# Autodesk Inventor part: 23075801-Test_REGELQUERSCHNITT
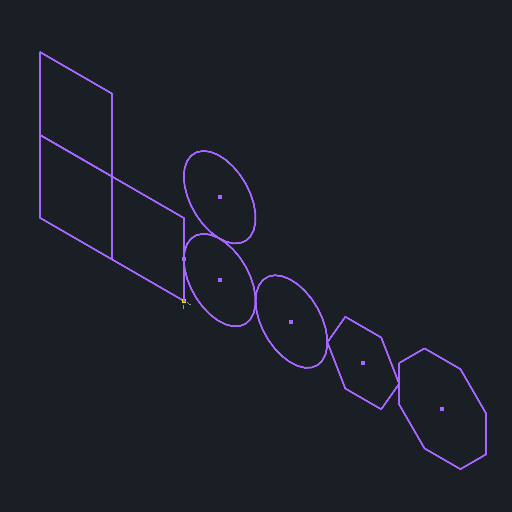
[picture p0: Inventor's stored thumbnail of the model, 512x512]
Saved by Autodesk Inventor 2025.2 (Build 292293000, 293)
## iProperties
Company: Ed. Züblin AG
Created: 2025-03
Part Number: 23075801-Test_REGELQUERSCHNITT
Material: Stahlbeton C30/37
Document SubType Name: Modeling
Designer: FrodlSte
Density: 2.5 g/cm^3
Appearance: Beton C30/37
z_Bereich: Tunnelbau
z_Direktion: Tief- und Tunnelbau
z_Konzerneinheit: Zentrale Technik
z_Matchkey: =<z_Matchkey_010>_<z_Matchkey_020>_<z_Matchkey_030>_<z_Matchkey_040>_<z_Matchkey_050>_<z_Matchkey_060>_<z_Matchkey_070>_<z_Matchkey_080>_<z_Matchkey_090>_<z_Mat
cpiComponentType: Attribut
cpiFitMatchkey: =<z_Matchkey>
z_Matchkey_010: xxxxx
z_Matchkey_020: 5DTUB
z_Matchkey_030: xxx
z_Matchkey_040: xxx
z_Matchkey_050: xxx
z_Matchkey_060: xxx
z_Matchkey_070: xxx
z_Matchkey_080: xxx
z_Matchkey_090: xxx
z_Matchkey_100: xxx
z_Matchkey_110: xxx
z_Matchkey_120: xxxxxxx
z_Matchkey_130: xxxx
z_Matchkey_140: xxxx
DocNumber: 23075801-Test_Skelett.ipt
Folder: DL23075801-DE-Pfaffensteigtunnel\BIM\Testmodell
VDS_Category: 09 - BIM - Konstruktion
d4: 1,000 m
d5: 1,000 m
d6: 1,000 m
d7: 1,000 m
d8: 1,000 m
d9: 1,000 m
d10: 1,000 m
d11: 1,000 m
d12: 1,000 m
d13: 0,500 m
d15: 0,500 m
AS_Ta_IST: 0,300 m
AS_Abs_L_So: 2,000 m
AS_Td_IST: 3,000 m
AS_Ti_IST: 3,000 m
AS_U_IST: 4,000 m
IS_T_b_M1: 1,000 m
AS_Abs_L_Ka: 1,000 m
DR_D_i: 0,250 m
AS_Dak_IST: 0,030 m
AS_Dad_IST: 0,010 m
Author: FrodlSte
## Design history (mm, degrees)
node "Blöcke"
  sketch "Baugruppe_Quadrate"
    geometry: L1 (0, 0)-(1000, 0); L2 (1000, 0)-(1000, 1000); L3 (1000, 1000)-(0, 1000); L4 (0, 1000)-(0, 0); L5 (1000, 0)-(2000, 0); L6 (2000, 0)-(2000, 1000); L7 (2000, 1000)-(1000, 1000); L8 (1000, 1000)-(1000, 0); L9 (1000, 1000)-(2000, 1000); L10 (2000, 1000)-(2000, 2000); L11 (2000, 2000)-(1000, 2000); L12 (1000, 2000)-(1000, 1000); 3 further points
    constraints: 24 end point, 6 parallel, 3 horizontal, 3 perpendicular, 2 coincident, 1 midpoint
    dimensions: "d4" = 1000 distance of L3.end L2.end (= Breite); "d5" = 1000 distance of L1.end L2.end (= Höhe); "d6" = 1000 distance of L7.end L6.end (= Breite); "d7" = 1000 distance of L5.end L6.end (= Höhe); "d8" = 1000 distance of L11.end L10.end (= Breite); "d9" = 1000 distance of L10.end L9.end (= Höhe)
  sketch "Baugruppe_Kreise"
    geometry: C1 r 500 at (-500, 500); C2 r 500 at (-1500, 500); C3 r 500 at (-500, 1500); 2 further points
    constraints: 3 centre point, 2 equal radius, 1 coincident, 1 horizontal alignment, 1 vertical alignment
    dimensions: "d10" = 1000 diameter of C1 (= Durchmesser); "d11" = 1000 diameter of C2 (= Durchmesser); "d12" = 1000 diameter of C3 (= Durchmesser)
  sketch "Bauteil_Sechseck"
    geometry: L1 (-2250, 933.013)-(-2000, 500); L2 (-2000, 500)-(-2250, 66.987); L3 (-2250, 66.987)-(-2750, 66.987); L4 (-2750, 66.987)-(-3000, 500); L5 (-3000, 500)-(-2750, 933.013); L6 (-2750, 933.013)-(-2250, 933.013); 3 further points
    constraints: 12 end point, 1 horizontal, 13 other
    dimensions: "d13" = 500 distance of L5.end L1.start (= Kantenlänge)
  sketch "Bauteil_Achteck"
    geometry: L1 (-3353.553, 1103.553)-(-3000, 750); L2 (-3000, 250)-(-3353.553, -103.553); L3 (-3353.553, -103.553)-(-3853.553, -103.553); L4 (-3853.553, -103.553)-(-4207.107, 250); L5 (-4207.107, 250)-(-4207.107, 750); L6 (-4207.107, 750)-(-3853.553, 1103.553); L7 (-3853.553, 1103.553)-(-3353.553, 1103.553); L8 (-3000, 750)-(-3000, 250); 2 further points
    constraints: 16 end point, 1 coincident, 1 horizontal, 1 vertical
    dimensions: "d15" = 500 distance of L6.end L1.start (= Kantenlänge)
sketch "Skizze3"
  geometry: 2 further points
  constraints: 2 other
  node "Baugruppe_Quadrate:1"
  node "Baugruppe_Kreise:1"
  node "Bauteil_Sechseck:1"
  node "Bauteil_Achteck:1"
node "Volumenkörper2"
node "Volumenkörpern"
node "Oberflächenkörpern"
other parameters: "Breite" = 1000 [user parameter; used in 3 equation terms], "Höhe" = 1000 [user parameter; used in 3 equation terms], "Kantenlänge" = 500 [user parameter; used in 2 equation terms], "Durchmesser" = 1000 [user parameter; used in 3 equation terms], "AS_Ta_IST" = 300 [user parameter], "AS_Abs_L_So" = 2000 [user parameter], "AS_Td_IST" = 3000 [user parameter], "AS_Ti_IST" = 3000 [user parameter], "AS_U_IST" = 4000 [user parameter], "IS_T_b_M1" = 1000 [user parameter], "AS_Abs_L_Ka" = 1000 [user parameter], "DR_D_i" = 250 [user parameter], "AS_Dak_IST" = 30 [user parameter], "AS_Dad_IST" = 10 [user parameter]
